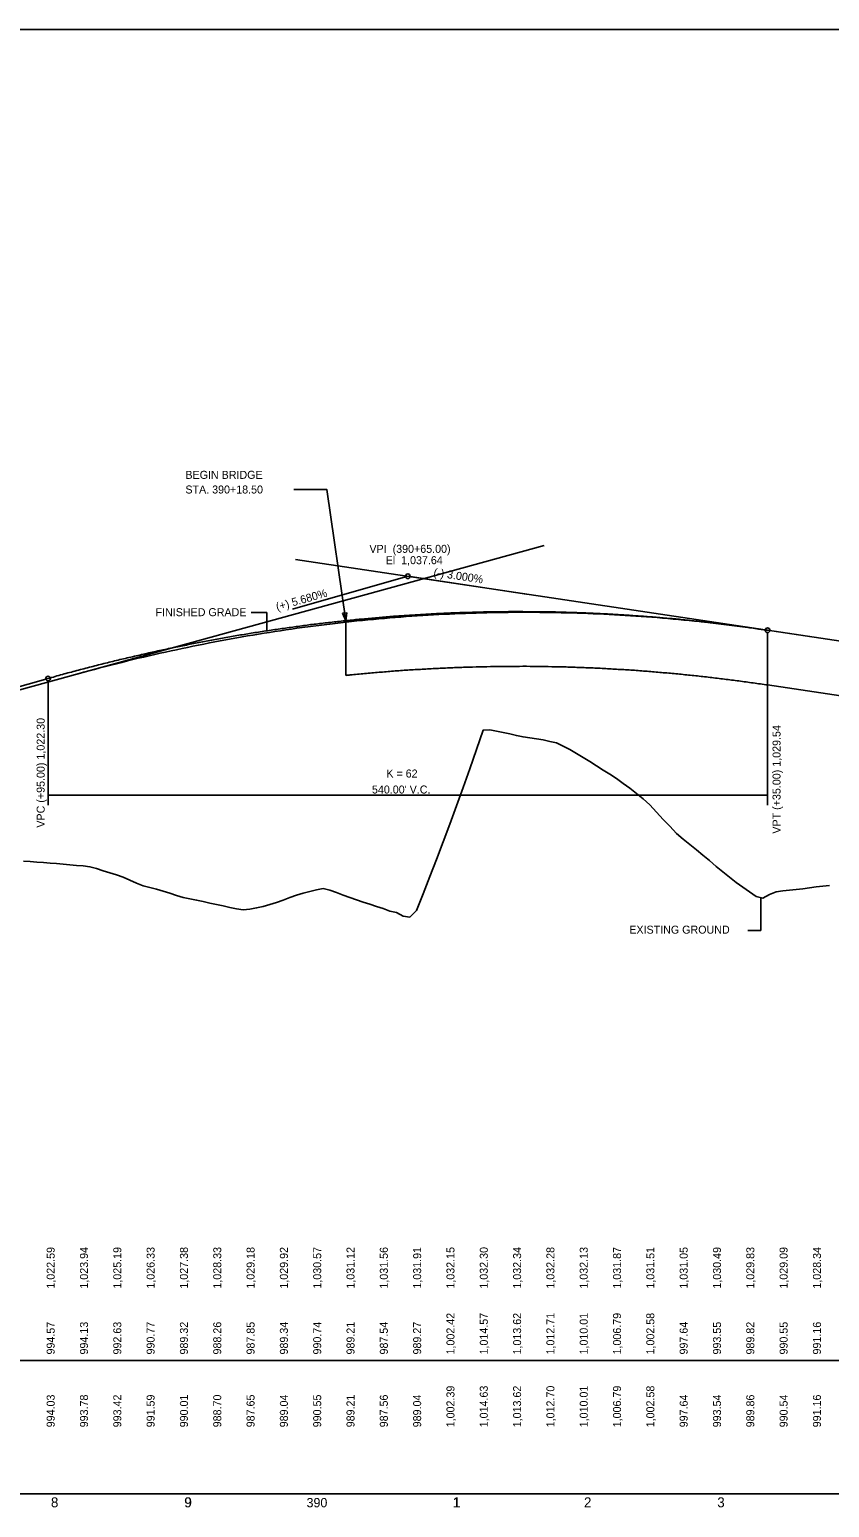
# Model space of a CAD drawing. Extents: x 150 to 16976893, y 3102 to 12559827.
# Drawn here: x 16973174 to 16973774, y 12558429 to 12559538 of the extents above; entities that cross this region are included whole.
import ezdxf

# ---------------------------------------------------------------- set-up
doc = ezdxf.new("R2010")
doc.units = 0
for name, color, linetype in [('Default', 7, 'Continuous'), ('Level 56', 7, 'Continuous'), ('RD_DDB_Ex_Tx', 7, 'Continuous'), ('RD_DDB_GradeTX', 7, 'Continuous'), ('RD_DDB_PI', 7, 'Continuous'), ('RD_DDB_Pr_Tx', 7, 'Continuous'), ('RD_DDB_Profile_EX', 7, 'Continuous'), ('RD_DDB_StaTX', 7, 'Continuous'), ('RD_DDB_StripGrade_EX', 7, 'Continuous'), ('RD_GPK_Profile_Cell', 7, 'Continuous'), ('RD_HC_TX_Sta20', 7, 'Continuous'), ('RD_PD_Bridge', 7, 'Continuous'), ('RD_PD_PatLn_I85', 7, 'Continuous'), ('RD_XS_Misc_Line', 7, 'Continuous')]:
    doc.layers.add(name, color=color, linetype=linetype)

msp = doc.modelspace()

# ---------------------------------------------------------------- linework, layer by layer
at = {"layer": 'Default'}
for p, q in [((16972821.8, 12558947.5), (16973560.3, 12559150.6)), ((16973373.6, 12559140.2), (16973787.9, 12559078))]:
    msp.add_line(p, q, dxfattribs=at)
msp.add_lwpolyline([(16972392.9, 12558539.3), (16973892.9, 12558539.3), (16973892.9, 12559537.5), (16972392.9, 12559537.5)], close=True, dxfattribs=at)
msp.add_open_spline([(16973210.5, 12559054.4), (16973469.8, 12559125.7), (16973729, 12559086.8)], degree=2, dxfattribs=at)
at = {"layer": 'RD_DDB_Ex_Tx'}
for p, q in [((16973722.7, 12558862), (16973722.7, 12558885.9)), ((16973713, 12558862), (16973722.7, 12558862))]:
    msp.add_line(p, q, dxfattribs=at)
at = {"layer": 'RD_DDB_PI'}
for p, q in [((16973371.3, 12559102.9), (16973456.2, 12559127)), ((16973546.9, 12559114.2), (16973459.6, 12559127.3))]:
    msp.add_line(p, q, dxfattribs=at)
msp.add_circle((16973457.9, 12559127.5), 1.75, dxfattribs=at)
at = {"layer": 'RD_DDB_Pr_Tx'}
for p, q in [((16973340.3, 12559100.4), (16973352.2, 12559100.4)), ((16973352.2, 12559100.4), (16973352.2, 12559086.6))]:
    msp.add_line(p, q, dxfattribs=at)
at = {"layer": 'RD_DDB_Profile_EX'}
for points in [[(16973259.4, 12558895.4), (16973264.4, 12558894.1), (16973269.4, 12558892.8), (16973274.4, 12558891.5), (16973279.4, 12558889.8), (16973284.4, 12558888.2), (16973289.4, 12558886.7), (16973294.4, 12558885.6), (16973299.4, 12558884.7), (16973304.4, 12558883.6), (16973309.4, 12558882.5), (16973314.4, 12558881.4), (16973319.4, 12558880.3), (16973324.4, 12558879.2), (16973329.4, 12558878.2), (16973334.4, 12558877.3), (16973339.4, 12558878), (16973344.4, 12558878.8), (16973349.4, 12558879.8), (16973354.4, 12558881.4), (16973359.4, 12558883), (16973364.4, 12558884.6), (16973369.4, 12558886.6), (16973374.4, 12558888.4), (16973379.4, 12558890), (16973384.4, 12558891.2), (16973389.4, 12558892.3), (16973394.4, 12558893.3), (16973399.4, 12558892.1), (16973404.4, 12558890.3), (16973409.4, 12558888.5), (16973414.4, 12558886.7), (16973419.4, 12558884.8), (16973424.4, 12558883.2), (16973429.4, 12558881.6), (16973434.4, 12558880), (16973439.4, 12558878.4), (16973444.4, 12558876.4), (16973449.4, 12558875.4), (16973454.4, 12558872.7), (16973459.4, 12558871.9), (16973464.4, 12558876.9), (16973469.4, 12558889.3), (16973474.4, 12558902.3), (16973479.4, 12558915.2), (16973484.4, 12558928.3), (16973489.4, 12558941.7), (16973494.4, 12558955.4), (16973499.4, 12558969.2), (16973504.4, 12558983.1), (16973509.4, 12558997.5), (16973514.4, 12559012), (16973519.4, 12559012.3), (16973524.4, 12559011.4), (16973529.4, 12559010.4), (16973534.4, 12559009.3), (16973539.4, 12559008.1), (16973544.4, 12559007.1), (16973549.4, 12559006.3), (16973554.4, 12559005.5), (16973559.4, 12559004.8), (16973564.4, 12559003.7), (16973569.4, 12559002.5), (16973574.4, 12559000.1), (16973579.4, 12558997.6), (16973584.4, 12558994.6), (16973589.4, 12558991.6), (16973594.4, 12558988.5), (16973599.4, 12558985.3), (16973604.4, 12558982.2), (16973609.4, 12558979), (16973614.4, 12558975.8), (16973619.4, 12558972.2), (16973624.4, 12558968.5), (16973629.4, 12558964.5), (16973634.4, 12558960.6), (16973639.4, 12558956.1), (16973644.4, 12558950.6), (16973649.4, 12558945.2), (16973654.4, 12558940), (16973659.4, 12558934.7), (16973664.4, 12558930.4), (16973669.4, 12558926.4), (16973674.4, 12558922.3), (16973679.4, 12558918.3), (16973684.4, 12558914.3), (16973689.4, 12558909.8), (16973694.4, 12558905.9), (16973699.4, 12558901.9), (16973704.4, 12558897.9), (16973709.4, 12558894.3), (16973714.4, 12558890.8), (16973719.4, 12558887.4), (16973724.4, 12558886.1), (16973729.4, 12558888.8), (16973734.4, 12558891), (16973739.4, 12558891.7), (16973744.4, 12558892.2), (16973749.4, 12558892.6), (16973754.4, 12558893.2), (16973759.4, 12558893.9)], [(16973169.4, 12558913.8), (16973174.4, 12558913.5), (16973179.4, 12558913.1), (16973184.4, 12558912.8), (16973189.4, 12558912.4), (16973194.4, 12558912.1), (16973199.4, 12558911.6), (16973204.4, 12558911.2), (16973209.4, 12558910.7), (16973214.4, 12558910.4), (16973219.4, 12558909.7), (16973224.4, 12558908.4), (16973229.4, 12558906.7), (16973234.4, 12558905.2), (16973239.4, 12558903.7), (16973244.4, 12558901.9), (16973249.4, 12558899.6), (16973254.4, 12558897.5), (16973259.4, 12558895.4)], [(16973759.4, 12558893.9), (16973764.4, 12558894.7), (16973769.4, 12558895.2), (16973774.4, 12558895.7)]]:
    msp.add_lwpolyline(points, dxfattribs=at)
at = {"layer": 'RD_GPK_Profile_Cell'}
msp.add_line((16972208.1, 12558439.3), (16976677.1, 12558439.3), dxfattribs=at)
at = {"layer": 'RD_HC_TX_Sta20'}
for p, q in [((16973727.9, 12558955.8), (16973727.9, 12559085.3)), ((16973187.9, 12558955.8), (16973187.9, 12559049.1)), ((16973187.9, 12558963.3), (16973727.9, 12558963.3))]:
    msp.add_line(p, q, dxfattribs=at)
for centre in [(16973727.9, 12559087), (16973187.9, 12559050.8)]:
    msp.add_circle(centre, 1.75, dxfattribs=at)
at = {"layer": 'RD_PD_Bridge'}
for p, q in [((16973411.4, 12559053.2), (16973411.4, 12559094.2)), ((16973727.9, 12559046), (16973787.9, 12559037))]:
    msp.add_line(p, q, dxfattribs=at)
msp.add_spline([(16973411.4, 12559053.2), (16973414.7, 12559053.5), (16973425.5, 12559054.6), (16973436.3, 12559055.5), (16973447.1, 12559056.4), (16973457.9, 12559057.2), (16973468.7, 12559057.8), (16973479.5, 12559058.4), (16973490.3, 12559058.9), (16973501.1, 12559059.3), (16973511.9, 12559059.6), (16973522.7, 12559059.8), (16973533.5, 12559059.9), (16973544.3, 12559060), (16973555.1, 12559059.9), (16973565.9, 12559059.7), (16973576.7, 12559059.5), (16973587.5, 12559059.1), (16973598.3, 12559058.7), (16973609.1, 12559058.1), (16973619.9, 12559057.5), (16973630.7, 12559056.8), (16973641.5, 12559055.9), (16973652.3, 12559055), (16973663.1, 12559054), (16973673.9, 12559052.9), (16973684.7, 12559051.7), (16973695.5, 12559050.4), (16973706.3, 12559049), (16973717.1, 12559047.5), (16973727.9, 12559046)], degree=3, dxfattribs=at)
at = {"layer": 'RD_PD_PatLn_I85'}
msp.add_lwpolyline([(16973372.4, 12559192.6), (16973397.2, 12559192.6), (16973411.4, 12559094.2)], dxfattribs=at)
msp.add_lwpolyline([(16973409, 12559099.8), (16973411.4, 12559094.2), (16973412.1, 12559100.2)], close=True, dxfattribs=at)
at = {"layer": 'RD_XS_Misc_Line'}
for p, q in [((16973727.9, 12559087), (16973787.9, 12559078)), ((16973157.9, 12559042.3), (16973187.9, 12559050.8))]:
    msp.add_line(p, q, dxfattribs=at)
msp.add_spline([(16973187.9, 12559050.8), (16973198.7, 12559053.9), (16973209.5, 12559056.8), (16973220.3, 12559059.6), (16973231.1, 12559062.4), (16973241.9, 12559065), (16973252.7, 12559067.5), (16973263.5, 12559070), (16973274.3, 12559072.4), (16973285.1, 12559074.6), (16973295.9, 12559076.8), (16973306.7, 12559078.9), (16973317.5, 12559080.9), (16973328.3, 12559082.8), (16973339.1, 12559084.6), (16973349.9, 12559086.3), (16973360.7, 12559087.9), (16973371.5, 12559089.4), (16973382.3, 12559090.9), (16973393.1, 12559092.2), (16973403.9, 12559093.4), (16973414.7, 12559094.6), (16973425.5, 12559095.6), (16973436.3, 12559096.6), (16973447.1, 12559097.5), (16973457.9, 12559098.2), (16973468.7, 12559098.9), (16973479.5, 12559099.5), (16973490.3, 12559100), (16973501.1, 12559100.4), (16973511.9, 12559100.7), (16973522.7, 12559100.9), (16973533.5, 12559101), (16973544.3, 12559101), (16973555.1, 12559100.9), (16973565.9, 12559100.8), (16973576.7, 12559100.5), (16973587.5, 12559100.2), (16973598.3, 12559099.7), (16973609.1, 12559099.2), (16973619.9, 12559098.5), (16973630.7, 12559097.8), (16973641.5, 12559097), (16973652.3, 12559096.1), (16973663.1, 12559095.1), (16973673.9, 12559093.9), (16973684.7, 12559092.7), (16973695.5, 12559091.5), (16973706.3, 12559090.1), (16973717.1, 12559088.6), (16973727.9, 12559087)], degree=3, dxfattribs=at)

# ---------------------------------------------------------------- texts
at = {"layer": 'Level 56'}
for s, p in [('1,022.59', (16973192.9, 12558593.3)), ('1,023.94', (16973217.9, 12558593.3)), ('1,025.19', (16973242.9, 12558593.3)), ('1,026.33', (16973267.9, 12558593.3)), ('1,027.38', (16973292.9, 12558593.3)), ('1,028.33', (16973317.9, 12558593.3)), ('1,029.18', (16973342.9, 12558593.3)), ('1,029.92', (16973367.9, 12558593.3)), ('1,030.57', (16973392.9, 12558593.3)), ('1,031.12', (16973417.9, 12558593.3)), ('1,031.56', (16973442.9, 12558593.3)), ('1,031.91', (16973467.9, 12558593.3)), ('1,032.15', (16973492.9, 12558593.3)), ('1,032.30', (16973517.9, 12558593.3)), ('1,032.34', (16973542.9, 12558593.3)), ('1,032.28', (16973567.9, 12558593.3)), ('1,032.13', (16973592.9, 12558593.3)), ('1,031.87', (16973617.9, 12558593.3)), ('1,031.51', (16973642.9, 12558593.3)), ('1,031.05', (16973667.9, 12558593.3)), ('1,030.49', (16973692.9, 12558593.3)), ('1,029.83', (16973717.9, 12558593.3)), ('1,029.09', (16973742.9, 12558593.3)), ('1,028.34', (16973767.9, 12558593.3)), ('989.04', (16973367.9, 12558489.3)), ('989.04', (16973467.9, 12558489.3)), ('1,002.39', (16973492.9, 12558489.3)), ('1,014.63', (16973517.9, 12558489.3)), ('1,013.62', (16973542.9, 12558489.3)), ('1,012.70', (16973567.9, 12558489.3)), ('1,010.01', (16973592.9, 12558489.3)), ('1,006.79', (16973617.9, 12558489.3)), ('1,002.58', (16973642.9, 12558489.3)), ('997.64', (16973667.9, 12558489.3)), ('993.54', (16973692.9, 12558489.3)), ('990.54', (16973742.9, 12558489.3)), ('994.03', (16973192.9, 12558489.3)), ('993.78', (16973217.9, 12558489.3)), ('993.42', (16973242.9, 12558489.3)), ('991.59', (16973267.9, 12558489.3)), ('990.01', (16973292.9, 12558489.3)), ('988.70', (16973317.9, 12558489.3)), ('987.65', (16973342.9, 12558489.3)), ('990.55', (16973392.9, 12558489.3)), ('989.21', (16973417.9, 12558489.3)), ('987.56', (16973442.9, 12558489.3)), ('989.86', (16973717.9, 12558489.3)), ('991.16', (16973767.9, 12558489.3))]:
    msp.add_text(s, height=6, rotation=90, dxfattribs=at).set_placement(p)
at = {"layer": 'RD_DDB_Ex_Tx'}
msp.add_text('EXISTING GROUND', height=6, dxfattribs=at).set_placement((16973624.1, 12558859.5))
at = {"layer": 'RD_DDB_GradeTX'}
for s, rotation, p in [('(-) 3.000%', 351.4692, (16973476.9, 12559127.7)), ('(+) 5.680%', 15.8556, (16973359.9, 12559101.6))]:
    msp.add_text(s, height=6, rotation=rotation, dxfattribs=at).set_placement(p)
at = {"layer": 'RD_DDB_PI'}
for s, p in [('VPI  (390+65.00)', (16973429.1, 12559145.1)), ('El  1,037.64', (16973441.3, 12559136.6))]:
    msp.add_text(s, height=6, dxfattribs=at).set_placement(p)
at = {"layer": 'RD_DDB_Pr_Tx'}
msp.add_text('FINISHED GRADE', height=6, dxfattribs=at).set_placement((16973268.6, 12559097.6))
at = {"layer": 'RD_DDB_StaTX'}
for s, height, p in [('8', 7.5, (16973190.1, 12558429.3)), ('8', 7.5, (16973190.1, 12558429.3)), ('9', 7.5, (16973290.1, 12558429.3)), ('9', 7.5, (16973290.3, 12558429.3)), ('390', 7, (16973381.9, 12558429.3)), ('390', 7, (16973381.9, 12558429.3)), ('1', 7.5, (16973491.6, 12558429.3)), ('1', 7.5, (16973491.9, 12558429.3)), ('2', 7.5, (16973590.1, 12558429.3)), ('2', 7.5, (16973590.1, 12558429.3)), ('3', 7.5, (16973690.1, 12558429.3)), ('3', 7.5, (16973690.1, 12558429.3))]:
    msp.add_text(s, height=height, dxfattribs=at).set_placement(p)
at = {"layer": 'RD_DDB_StripGrade_EX'}
for s, p in [('1,002.42', (16973492.9, 12558543.9)), ('1,014.57', (16973517.9, 12558543.9)), ('1,013.62', (16973542.9, 12558543.9)), ('1,012.71', (16973567.9, 12558543.9)), ('1,010.01', (16973592.9, 12558543.9)), ('1,006.79', (16973617.9, 12558543.9)), ('1,002.58', (16973642.9, 12558543.9)), ('994.57', (16973192.9, 12558543.9)), ('994.13', (16973217.9, 12558543.9)), ('992.63', (16973242.9, 12558543.9)), ('990.77', (16973267.9, 12558543.9)), ('989.32', (16973292.9, 12558543.9)), ('988.26', (16973317.9, 12558543.9)), ('987.85', (16973342.9, 12558543.9)), ('989.34', (16973367.9, 12558543.9)), ('990.74', (16973392.9, 12558543.9)), ('989.21', (16973417.9, 12558543.9)), ('987.54', (16973442.9, 12558543.9)), ('989.27', (16973467.9, 12558543.9)), ('997.64', (16973667.9, 12558543.9)), ('993.55', (16973692.9, 12558543.9)), ('989.82', (16973717.9, 12558543.9)), ('990.55', (16973742.9, 12558543.9)), ('991.16', (16973767.9, 12558543.9))]:
    msp.add_text(s, height=6, rotation=90, dxfattribs=at).set_placement(p)
at = {"layer": 'RD_HC_TX_Sta20'}
for s, p in [('VPC (+95.00) 1,022.30', (16973185.4, 12558939)), ('VPT (+35.00) 1,029.54', (16973737.6, 12558934.5))]:
    msp.add_text(s, height=6, rotation=90, dxfattribs=at).set_placement(p)
for s, p in [('K = 62', (16973441.8, 12558976.6)), ("540.00' V.C.", (16973431, 12558964.6))]:
    msp.add_text(s, height=6, dxfattribs=at).set_placement(p)
at = {"layer": 'RD_PD_PatLn_I85'}
for s, p in [('BEGIN BRIDGE', (16973291, 12559200.6)), ('STA. 390+18.50', (16973291, 12559189.6))]:
    msp.add_text(s, height=6, rotation=360, dxfattribs=at).set_placement(p)

doc.saveas('drawing.dxf')
